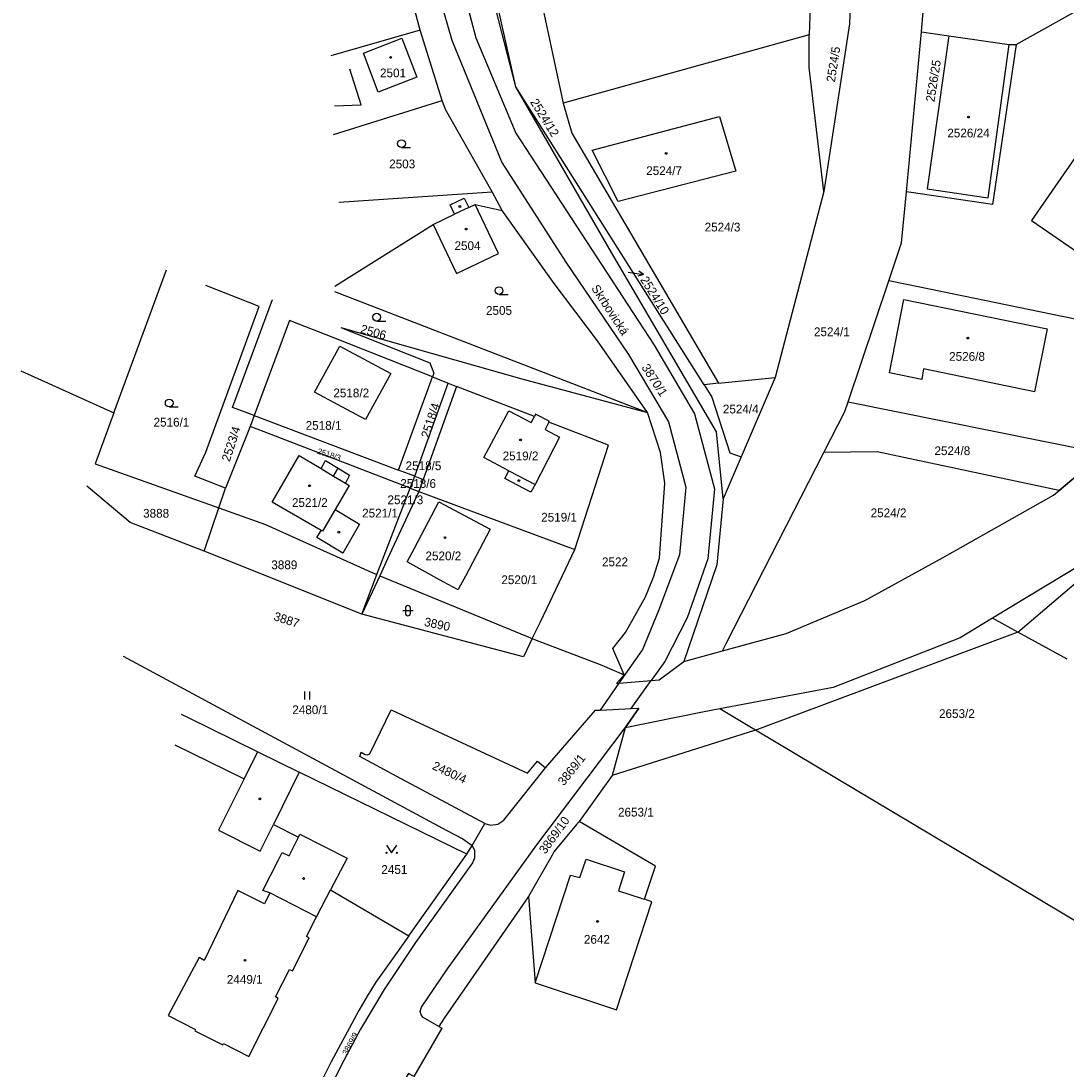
# Model space of a CAD drawing. Extents: x -527335 to -526256, y -1079142 to -1077809.
# Drawn here: x -527335.2 to -527132.2, y -1078645.5 to -1078442 of the extents above; entities that cross this region are included whole.
import ezdxf

# ---------------------------------------------------------------- set-up
doc = ezdxf.new("R2010")
doc.units = 0
for name, color, linetype in [('Vrstva 1', 7, 'Continuous'), ('Vrstva 2', 7, 'Continuous'), ('Vrstva 3', 7, 'Continuous'), ('Vrstva 4', 7, 'Continuous'), ('Vrstva 5', 7, 'Continuous'), ('Vrstva 54', 7, 'Continuous'), ('Vrstva 7', 7, 'Continuous')]:
    doc.layers.add(name, color=color, linetype=linetype)

msp = doc.modelspace()

# ---------------------------------------------------------------- linework, layer by layer
at = {"layer": 'Vrstva 1'}
for p, q in [((-527239.04, -1078454.82), (-527247.66, -1078421.31)), ((-527239.04, -1078454.82), (-527244.36, -1078431)), ((-527235.72, -1078430.51), (-527229.87, -1078457.96)), ((-527181.65, -1078433.18), (-527182.05, -1078444.72)), ((-527160.26, -1078444.15), (-527159.81, -1078439.41)), ((-527257.62, -1078443.82), (-527275, -1078448.78)), ((-527253.34, -1078457.46), (-527257.62, -1078443.82)), ((-527182.05, -1078444.72), (-527229.87, -1078457.96)), ((-527163.17, -1078475.2), (-527160.26, -1078444.15)), ((-527160.26, -1078444.15), (-527154.89, -1078444.92)), ((-527154.89, -1078444.92), (-527143.23, -1078446.59)), ((-527143.23, -1078446.59), (-527141.86, -1078446.59)), ((-527202.47, -1078512.66), (-527239.04, -1078454.82)), ((-527274.44, -1078464.05), (-527253.34, -1078457.46)), ((-527273.4, -1078477.22), (-527243.62, -1078475.21)), ((-527241.72, -1078478.83), (-527243.62, -1078475.21)), ((-527179.21, -1078475.16), (-527188.68, -1078511.23)), ((-527317.13, -1078518.14), (-527306.91, -1078490.33)), ((-527174.49, -1078515.96), (-527166.58, -1078492.47)), ((-527274.23, -1078494.55), (-527213.45, -1078518.05)), ((-527335.17, -1078509.94), (-527317.13, -1078518.14)), ((-527261.81, -1078529.25), (-527255.24, -1078511.13)), ((-527258.66, -1078530.43), (-527252.15, -1078512.35)), ((-527255.24, -1078511.13), (-527252.15, -1078512.35)), ((-527252.15, -1078512.35), (-527250.53, -1078512.99)), ((-527199.68, -1078512.37), (-527202.47, -1078512.66)), ((-527199.68, -1078512.37), (-527188.68, -1078511.23)), ((-527188.68, -1078511.23), (-527195.25, -1078526.63)), ((-527250.53, -1078512.99), (-527257.05, -1078531.04)), ((-527235.44, -1078518.84), (-527250.53, -1078512.99)), ((-527174.49, -1078515.96), (-527124.9, -1078525.93)), ((-527317.13, -1078518.14), (-527320.76, -1078528.03)), ((-527289.88, -1078518.66), (-527290.67, -1078520.76)), ((-527289.88, -1078518.66), (-527261.81, -1078529.25)), ((-527290.67, -1078520.76), (-527295.46, -1078532.72)), ((-527195.25, -1078526.63), (-527198.73, -1078534.79)), ((-527124.9, -1078525.93), (-527133.51, -1078533.2)), ((-527320.76, -1078528.03), (-527296.75, -1078536.57)), ((-527258.66, -1078530.43), (-527261.81, -1078529.25)), ((-527259.56, -1078532.72), (-527258.66, -1078530.43)), ((-527258.66, -1078530.43), (-527257.05, -1078531.04)), ((-527296.75, -1078536.57), (-527295.46, -1078532.72)), ((-527266.02, -1078549.53), (-527259.56, -1078532.72)), ((-527259.56, -1078532.72), (-527257.89, -1078533.36)), ((-527257.05, -1078531.04), (-527257.89, -1078533.36)), ((-527257.89, -1078533.36), (-527227.55, -1078544.64)), ((-527299.55, -1078544.94), (-527296.75, -1078536.57)), ((-527268.92, -1078557.21), (-527299.55, -1078544.94)), ((-527268.92, -1078557.21), (-527266.02, -1078549.53)), ((-527265.48, -1078549.77), (-527268.92, -1078557.21)), ((-527265.48, -1078549.77), (-527235.84, -1078561.93)), ((-527206.43, -1078566.42), (-527198.92, -1078564.35)), ((-527233.27, -1078587.02), (-527223.54, -1078575.86)), ((-527248.53, -1078603.79), (-527281.11, -1078587.88)), ((-527247.54, -1078602.12), (-527245.03, -1078597.85)), ((-527259.82, -1078619.66), (-527248.53, -1078603.79)), ((-527248.53, -1078603.79), (-527247.54, -1078602.12))]:
    msp.add_line(p, q, dxfattribs=at)
for points in [[(-527257.62, -1078443.82), (-527260.56, -1078432.84), (-527263.99, -1078416.01), (-527265.53, -1078409.01), (-527266.79, -1078407.04)], [(-527141.86, -1078446.59), (-527110.16, -1078428.84), (-527097.36, -1078410.28)], [(-527092.4, -1078413.63), (-527138.83, -1078480.75), (-527128.47, -1078487.92), (-527076.74, -1078413.16)], [(-527173.99, -1078435.36), (-527174.21, -1078442.61), (-527179.21, -1078475.16)], [(-527179.21, -1078475.16), (-527182.08, -1078451.08), (-527182.05, -1078444.72)], [(-527154.89, -1078444.92), (-527159.14, -1078474.62), (-527147.28, -1078476.36), (-527143.23, -1078446.59)], [(-527141.86, -1078446.59), (-527146.45, -1078477.67), (-527162.26, -1078475.33), (-527163.17, -1078475.2)], [(-527198.73, -1078534.79), (-527200.06, -1078521.8), (-527220.43, -1078486.97), (-527239.04, -1078454.82)], [(-527243.62, -1078475.21), (-527252.7, -1078459.24), (-527253.34, -1078457.46)], [(-527229.87, -1078457.96), (-527228.18, -1078463.81), (-527199.68, -1078512.37)], [(-527219.15, -1078477.07), (-527224.21, -1078467.12), (-527199.45, -1078460.61), (-527196.27, -1078471.22), (-527219.15, -1078477.07)], [(-527068.91, -1078470.58), (-527076.43, -1078483.63), (-527090.99, -1078506.94), (-527111.43, -1078532.12), (-527128.98, -1078547.4), (-527146.41, -1078557.97)], [(-527166.58, -1078492.47), (-527164.1, -1078485.12), (-527163.17, -1078475.2)], [(-527274.18, -1078493.5), (-527255.07, -1078481.53), (-527250.55, -1078491.03), (-527242.42, -1078487.16), (-527246.95, -1078477.65), (-527241.72, -1078478.83)], [(-527213.45, -1078518.05), (-527223.17, -1078504.16), (-527231.59, -1078492.99), (-527241.72, -1078478.83)], [(-527295.46, -1078532.72), (-527301.38, -1078530.43), (-527299.24, -1078525.73), (-527288.92, -1078497.44), (-527299.25, -1078493.36)], [(-527104.6, -1078505.26), (-527106.49, -1078504.87), (-527163.05, -1078493.2), (-527166.58, -1078492.47)], [(-527289.88, -1078518.66), (-527294.09, -1078517.07), (-527286.31, -1078496.08)], [(-527166.45, -1078510.36), (-527163.63, -1078496.12), (-527135.81, -1078501.81), (-527138.3, -1078514.05), (-527159.84, -1078509.57), (-527160.15, -1078511.61), (-527166.45, -1078510.36)], [(-527255.24, -1078511.13), (-527274.39, -1078503.57), (-527282.98, -1078500.18), (-527289.88, -1078518.66)], [(-527273.06, -1078501.52), (-527237.85, -1078511.53), (-527213.45, -1078518.05)], [(-527273.06, -1078501.52), (-527255.77, -1078508.43), (-527254.97, -1078510.38), (-527255.24, -1078511.13)], [(-527268.22, -1078519.41), (-527278.14, -1078514.11), (-527273.23, -1078505.19), (-527263.34, -1078510.46), (-527268.22, -1078519.41)], [(-527202.47, -1078512.66), (-527200.97, -1078515.04), (-527197.46, -1078525.86), (-527195.25, -1078526.63)], [(-527179.2, -1078525.81), (-527175.13, -1078517.85), (-527174.49, -1078515.96)], [(-527232.64, -1078519.92), (-527233.36, -1078521.36), (-527230.53, -1078522.83), (-527235.31, -1078532.02), (-527236.1, -1078533.53), (-527241.2, -1078530.87), (-527240.4, -1078529.35), (-527245.27, -1078526.81), (-527240.41, -1078517.7), (-527236.03, -1078519.97), (-527235.44, -1078518.84)], [(-527232.64, -1078519.92), (-527232.55, -1078519.75), (-527235.19, -1078518.36), (-527235.44, -1078518.84)], [(-527217.99, -1078568.99), (-527220.17, -1078563.88), (-527217.74, -1078560.78), (-527213.84, -1078553.85), (-527212.32, -1078550.03), (-527211.14, -1078546.31), (-527210.11, -1078531.79), (-527210.95, -1078525.81), (-527213.45, -1078518.05)], [(-527227.55, -1078544.64), (-527221.02, -1078524.42), (-527232.64, -1078519.92)], [(-527259.56, -1078532.72), (-527286.59, -1078522.33), (-527290.67, -1078520.76)], [(-527273.54, -1078528.84), (-527271.32, -1078530.24), (-527272.15, -1078531.75), (-527271.41, -1078532.19), (-527274.14, -1078536.87), (-527269.43, -1078539.75), (-527272.61, -1078545.33), (-527277.67, -1078542.33), (-527276.85, -1078540.95), (-527286.39, -1078535.46), (-527281.11, -1078526.41), (-527276.87, -1078528.94), (-527276.02, -1078527.39), (-527273.54, -1078528.84)], [(-527198.92, -1078564.35), (-527198.17, -1078562.88), (-527179.2, -1078525.81)], [(-527133.51, -1078533.2), (-527168.85, -1078525.7), (-527179.2, -1078525.81)], [(-527299.55, -1078544.94), (-527313.94, -1078539.4), (-527322.05, -1078532.59), (-527322.35, -1078532.34)], [(-527257.89, -1078533.36), (-527263.95, -1078546.46), (-527265.48, -1078549.77)], [(-527198.73, -1078534.79), (-527200, -1078547.64), (-527206.43, -1078566.42)], [(-527198.92, -1078564.35), (-527186.55, -1078560.94), (-527171.22, -1078554.58), (-527156.15, -1078546.29), (-527134.58, -1078534.1), (-527133.51, -1078533.2)], [(-527296.75, -1078536.57), (-527287.69, -1078539.8), (-527267.27, -1078548.97), (-527266.02, -1078549.53)], [(-527254, -1078535.37), (-527244.02, -1078540.72), (-527248.84, -1078549.81), (-527250.09, -1078552.15), (-527250.26, -1078552.48), (-527253.13, -1078550.9), (-527260.15, -1078547.05), (-527258.75, -1078544.4), (-527254, -1078535.37)], [(-527235.84, -1078561.93), (-527234.27, -1078558.66), (-527227.55, -1078544.64)], [(-527235.84, -1078561.93), (-527237.54, -1078565.48), (-527268.92, -1078557.21)], [(-527146.41, -1078557.97), (-527152.71, -1078561.79), (-527177.41, -1078571.47), (-527199.41, -1078575.6)], [(-527131.94, -1078565.93), (-527141.5, -1078560.67), (-527146.41, -1078557.97)], [(-527235.84, -1078561.93), (-527235.43, -1078562.1), (-527222.35, -1078567.12), (-527217.99, -1078568.99)], [(-527217.99, -1078568.99), (-527219.46, -1078570.65), (-527218.96, -1078570.61), (-527212.76, -1078570.1), (-527211.21, -1078569.97), (-527206.43, -1078566.42)], [(-527223.54, -1078575.86), (-527222.6, -1078575.81), (-527216.65, -1078575.51), (-527215.15, -1078575.44), (-527217.79, -1078579.29)], [(-527304.05, -1078576.62), (-527302.7, -1078577.25), (-527289.18, -1078583.91), (-527281.11, -1078587.88)], [(-527269.35, -1078584.85), (-527269.09, -1078584.02), (-527268.28, -1078584.48), (-527267.9, -1078584.54), (-527267.39, -1078584.35), (-527263.26, -1078575.8), (-527236.76, -1078588.08), (-527234.83, -1078585.74), (-527233.27, -1078587.02)], [(-527199.41, -1078575.6), (-527202.75, -1078576.23), (-527217.79, -1078579.29)], [(-527116.37, -1078625.34), (-527123.55, -1078620.8), (-527150.28, -1078604.87), (-527192.47, -1078579.74), (-527193.56, -1078579.08), (-527199.41, -1078575.6)], [(-527254.01, -1078637.26), (-527257.04, -1078635.52), (-527257.44, -1078634.99), (-527257.59, -1078634.32), (-527257.37, -1078633.52), (-527252.31, -1078626.07), (-527234.96, -1078601.97), (-527217.79, -1078579.29)], [(-527217.79, -1078579.29), (-527220.33, -1078588.55), (-527226.74, -1078597.44)], [(-527245.03, -1078597.85), (-527262.18, -1078588.7), (-527269.35, -1078584.85)], [(-527245.03, -1078597.85), (-527243.94, -1078598.18), (-527242.52, -1078597.99), (-527241.39, -1078597.17), (-527233.27, -1078587.02)], [(-527281.11, -1078587.88), (-527286.12, -1078598.02), (-527281.28, -1078600.51), (-527280.99, -1078599.93), (-527271.78, -1078604.56), (-527275.02, -1078610.72), (-527259.82, -1078619.66)], [(-527226.74, -1078597.44), (-527227.25, -1078598.03), (-527231.63, -1078603.34), (-527231.98, -1078604), (-527236.58, -1078612)], [(-527236.58, -1078612), (-527235.31, -1078628.81), (-527219.47, -1078634.01), (-527212.59, -1078613.04), (-527214.07, -1078612.55), (-527211.93, -1078606.15), (-527226.74, -1078597.44)], [(-527247.54, -1078602.12), (-527247.04, -1078603.09), (-527247.06, -1078604.56), (-527247.44, -1078605.48), (-527258.5, -1078620.92), (-527264.64, -1078630.06), (-527269.21, -1078637.79), (-527272.96, -1078644.85), (-527276.06, -1078651.14), (-527277.91, -1078656.32)], [(-527236.58, -1078612), (-527252.96, -1078635.63), (-527254.01, -1078637.26)], [(-527259.82, -1078619.66), (-527262.34, -1078623.21), (-527266.21, -1078628.65), (-527267.92, -1078631.37), (-527269.54, -1078634.12), (-527274.93, -1078644.11), (-527277.98, -1078650.21), (-527279.35, -1078653.36)], [(-527254.01, -1078637.26), (-527253.42, -1078637.6), (-527258.88, -1078646.96), (-527259.9, -1078646.35), (-527260.95, -1078647.97)]]:
    msp.add_lwpolyline(points, dxfattribs=at)
at = {"layer": 'Vrstva 3'}
for p, q in [((-527261.24, -1078466.6), (-527259.49, -1078466.6)), ((-527242.3, -1078495.13), (-527240.55, -1078495.13)), ((-527266.06, -1078500.29), (-527264.31, -1078500.29)), ((-527306.37, -1078516.95), (-527304.62, -1078516.95)), ((-527261, -1078556.52), (-527259, -1078556.52)), ((-527260.5, -1078556.02), (-527260.5, -1078557.02)), ((-527259.5, -1078557.02), (-527259.5, -1078556.02)), ((-527280.05, -1078573.74), (-527280.05, -1078572.24)), ((-527279.05, -1078573.74), (-527279.05, -1078572.24))]:
    msp.add_line(p, q, dxfattribs=at)
msp.add_lwpolyline([(-527264.17, -1078602.04), (-527263.17, -1078603.54), (-527262.17, -1078602.04)], dxfattribs=at)
for centre, radius in [((-527261.24, -1078465.85), 0.75), ((-527242.3, -1078494.38), 0.75), ((-527266.06, -1078499.54), 0.75), ((-527306.37, -1078516.2), 0.75), ((-527264.17, -1078603.54), 0.1), ((-527262.17, -1078603.54), 0.1)]:
    msp.add_circle(centre, radius, dxfattribs=at)
for centre, start, end in [((-527260, -1078556.02), 0, 180), ((-527260, -1078557.02), 180, 359.9879)]:
    msp.add_arc(centre, 0.5, start, end, dxfattribs=at)
at = {"layer": 'Vrstva 4'}
for p, q in [((-527257.19, -1078425.85), (-527251.49, -1078445.79)), ((-527252.03, -1078425.08), (-527246.83, -1078445.33)), ((-527268.65, -1078448.3), (-527261.15, -1078445.39)), ((-527261.15, -1078445.39), (-527258.29, -1078452.93)), ((-527251.49, -1078445.79), (-527241.75, -1078469.5)), ((-527246.83, -1078445.33), (-527239.01, -1078463.8)), ((-527265.8, -1078455.86), (-527268.65, -1078448.3)), ((-527269.08, -1078458.33), (-527271.25, -1078451.41)), ((-527258.29, -1078452.93), (-527265.8, -1078455.86)), ((-527274.24, -1078458.53), (-527269.08, -1078458.33)), ((-527239.01, -1078463.8), (-527224.34, -1078486.36)), ((-527241.75, -1078469.5), (-527229.3, -1078488.84)), ((-527251.82, -1078477.73), (-527249.06, -1078476.42)), ((-527250.95, -1078479.56), (-527251.82, -1078477.73)), ((-527249.06, -1078476.42), (-527248.19, -1078478.25)), ((-527248.19, -1078478.25), (-527246.95, -1078477.65)), ((-527255.07, -1078481.53), (-527250.95, -1078479.56)), ((-527248.19, -1078478.25), (-527250.95, -1078479.56)), ((-527224.34, -1078486.36), (-527212.18, -1078504.95)), ((-527229.3, -1078488.84), (-527217.18, -1078506.82)), ((-527212.18, -1078504.95), (-527204.34, -1078518.29)), ((-527217.18, -1078506.82), (-527209.4, -1078519.86)), ((-527204.34, -1078518.29), (-527200.47, -1078532.85)), ((-527209.4, -1078519.86), (-527206.04, -1078532.55)), ((-527276.87, -1078528.94), (-527274.45, -1078530.38)), ((-527274.45, -1078530.38), (-527273.54, -1078528.84)), ((-527274.45, -1078530.38), (-527272.15, -1078531.75)), ((-527240.4, -1078529.35), (-527235.31, -1078532.02)), ((-527206.04, -1078532.55), (-527207.21, -1078545.66)), ((-527200.47, -1078532.85), (-527201.76, -1078546.48)), ((-527141.5, -1078560.67), (-527109.01, -1078533.01)), ((-527274.14, -1078536.87), (-527276.6, -1078541.09)), ((-527276.6, -1078541.09), (-527276.85, -1078540.95)), ((-527207.21, -1078545.66), (-527211.24, -1078556.37)), ((-527201.76, -1078546.48), (-527205.76, -1078557.93)), ((-527211.24, -1078556.37), (-527214.52, -1078564.26)), ((-527205.76, -1078557.93), (-527210.09, -1078566.38)), ((-527141.5, -1078560.67), (-527192.07, -1078579.61)), ((-527315.29, -1078565.33), (-527252.47, -1078599.22)), ((-527218.96, -1078570.61), (-527214.52, -1078564.26)), ((-527210.09, -1078566.38), (-527212.76, -1078570.1)), ((-527222.6, -1078575.81), (-527218.96, -1078570.61)), ((-527216.65, -1078575.51), (-527212.76, -1078570.1)), ((-527192.47, -1078579.74), (-527220.33, -1078588.55)), ((-527192.07, -1078579.61), (-527192.47, -1078579.74)), ((-527305.27, -1078582.54), (-527291.79, -1078589.15)), ((-527291.79, -1078589.15), (-527289.18, -1078583.91)), ((-527291.79, -1078589.15), (-527296.8, -1078599.13)), ((-527296.8, -1078599.13), (-527288.7, -1078603.23)), ((-527288.7, -1078603.23), (-527286.12, -1078598.02)), ((-527252.47, -1078599.22), (-527249.31, -1078600.83)), ((-527249.31, -1078600.83), (-527247.54, -1078602.12)), ((-527226.61, -1078608.33), (-527225.35, -1078604.75)), ((-527225.35, -1078604.75), (-527217.95, -1078607.21)), ((-527235.31, -1078628.81), (-527228.42, -1078607.88)), ((-527228.42, -1078607.88), (-527226.61, -1078608.33)), ((-527217.95, -1078607.21), (-527219.07, -1078610.9)), ((-527293.03, -1078610.82), (-527299.57, -1078624.44)), ((-527287.83, -1078613.47), (-527293.03, -1078610.82)), ((-527286.82, -1078611.29), (-527287.83, -1078613.47)), ((-527277.77, -1078615.94), (-527286.82, -1078611.29)), ((-527277.77, -1078615.94), (-527275.02, -1078610.72)), ((-527219.07, -1078610.9), (-527214.52, -1078612.4)), ((-527214.52, -1078612.4), (-527214.07, -1078612.55)), ((-527279.72, -1078619.78), (-527277.77, -1078615.94)), ((-527282.45, -1078626.45), (-527279.19, -1078620.05)), ((-527279.19, -1078620.05), (-527279.72, -1078619.78)), ((-527300.52, -1078623.89), (-527306.58, -1078635.1)), ((-527299.57, -1078624.44), (-527300.52, -1078623.89)), ((-527285.72, -1078631.52), (-527282.99, -1078626.17)), ((-527282.99, -1078626.17), (-527282.45, -1078626.45)), ((-527290.93, -1078643.06), (-527285.18, -1078631.79)), ((-527285.18, -1078631.79), (-527285.72, -1078631.52)), ((-527306.58, -1078635.1), (-527301.23, -1078637.82)), ((-527301.23, -1078637.82), (-527301.36, -1078638.08)), ((-527301.36, -1078638.08), (-527295.95, -1078640.84)), ((-527295.95, -1078640.84), (-527295.82, -1078640.57)), ((-527295.82, -1078640.57), (-527290.93, -1078643.06))]:
    msp.add_line(p, q, dxfattribs=at)
for points in [[(-527285.18, -1078605.01), (-527284.4, -1078603.5), (-527283.09, -1078604.13), (-527281.28, -1078600.51)], [(-527286.82, -1078611.29), (-527288.18, -1078610.84), (-527285.18, -1078605.01)]]:
    msp.add_lwpolyline(points, dxfattribs=at)
at = {"layer": 'Vrstva 5'}
for centre in [(-527263.35, -1078449.1), (-527151.12, -1078460.69), (-527209.83, -1078467.74), (-527249.92, -1078478.05), (-527248.67, -1078482.43), (-527151.22, -1078503.6), (-527238.13, -1078523.37), (-527279.1, -1078532.27), (-527238.44, -1078531.27), (-527273.44, -1078541.28), (-527252.8, -1078542.34), (-527288.74, -1078593.05), (-527280.25, -1078608.51), (-527223.15, -1078616.85), (-527291.65, -1078624.4)]:
    msp.add_circle(centre, 0.175, dxfattribs=at)
at = {"layer": 'Vrstva 54'}
for points in [[(-527211.21, -1078569.97), (-527206.43, -1078566.42), (-527198.92, -1078564.35), (-527186.55, -1078560.94), (-527171.22, -1078554.58), (-527156.15, -1078546.29), (-527134.58, -1078534.1), (-527133.51, -1078533.2), (-527124.9, -1078525.93), (-527119.69, -1078521.54), (-527104.6, -1078505.26), (-527102.68, -1078503.19), (-527093.38, -1078489.99), (-527078.2, -1078464.76), (-527073.97, -1078460.17), (-527053.17, -1078420.48)], [(-527044.07, -1078424.46), (-527066.65, -1078463.1), (-527068.91, -1078470.58), (-527090.99, -1078506.94), (-527111.43, -1078532.12), (-527128.98, -1078547.4), (-527146.41, -1078557.97), (-527152.71, -1078561.79), (-527177.41, -1078571.47), (-527199.41, -1078575.6), (-527202.75, -1078576.23), (-527217.79, -1078579.29), (-527215.15, -1078575.44)]]:
    msp.add_lwpolyline(points, dxfattribs=at)
at = {"layer": 'Vrstva 7'}
for p, q in [((-527217.22, -1078490.78), (-527214.26, -1078491.25)), ((-527214.26, -1078491.25), (-527215.32, -1078491.59)), ((-527214.26, -1078491.25), (-527215.17, -1078490.6))]:
    msp.add_line(p, q, dxfattribs=at)

# ---------------------------------------------------------------- texts
at = {"layer": 'Vrstva 2'}
for s, height, rotation, p in [('2524/5', 1.7, 81, (-527177.06, -1078454.01)), ('2526/25', 1.7, 81, (-527157.73, -1078457.85)), ('2524/12', 1.7, 302, (-527236.32, -1078457.78)), ('2524/10', 1.7, 302, (-527214.93, -1078492.27)), ('2506', 1.7, 344, (-527269.36, -1078502.54)), ('3870/1', 1.7, 303, (-527214.69, -1078509.31)), ('2518/4', 1.7, 72, (-527255.89, -1078523.16)), ('2523/4', 1.7, 72, (-527294.62, -1078527.71)), ('2518/3', 1.139, 342, (-527277.7, -1078526.03)), ('3887', 1.7, 342, (-527286.22, -1078558.32)), ('3890', 1.7, 348, (-527256.95, -1078559.46)), ('3869/1', 1.7, 51.4372, (-527229.71, -1078590.63)), ('2480/4', 1.7, 335, (-527255.42, -1078587.23)), ('3869/10', 1.7, 54, (-527233.31, -1078603.91)), ('3869/9', 1.139, 62, (-527271.81, -1078642.9))]:
    msp.add_text(s, height=height, rotation=rotation, dxfattribs=at).set_placement(p)
for s, p in [('2501', (-527265.42, -1078452.97)), ('2526/24', (-527155.21, -1078464.64)), ('2503', (-527263.64, -1078470.64)), ('2524/7', (-527213.71, -1078471.95)), ('2524/3', (-527202.36, -1078482.9)), ('2504', (-527250.95, -1078486.51)), ('2505', (-527244.83, -1078499.09)), ('2524/1', (-527181.12, -1078503.23)), ('2526/8', (-527154.86, -1078508.01)), ('2518/2', (-527274.49, -1078515.1)), ('2524/4', (-527198.82, -1078518.23)), ('2516/1', (-527309.41, -1078520.78)), ('2518/1', (-527279.86, -1078521.41)), ('2524/8', (-527157.71, -1078526.32)), ('2519/2', (-527241.6, -1078527.33)), ('2518/5', (-527260.45, -1078529.24)), ('2518/6', (-527261.49, -1078532.68)), ('2521/2', (-527282.53, -1078536.38)), ('2521/3', (-527263.97, -1078535.85)), ('3888', (-527311.44, -1078538.47)), ('2521/1', (-527268.89, -1078538.43)), ('2524/2', (-527170.11, -1078538.38)), ('2519/1', (-527234.11, -1078539.23)), ('2520/2', (-527256.59, -1078546.74)), ('3889', (-527286.54, -1078548.47)), ('2522', (-527222.3, -1078547.9)), ('2520/1', (-527241.84, -1078551.37)), ('2480/1', (-527282.46, -1078576.61)), ('2653/2', (-527156.83, -1078577.36)), ('2653/1', (-527219.19, -1078596.49)), ('2451', (-527265.16, -1078607.63)), ('2642', (-527225.81, -1078621.19)), ('2449/1', (-527295.17, -1078628.96))]:
    msp.add_text(s, height=1.7, dxfattribs=at).set_placement(p)
at = {"layer": 'Vrstva 7'}
msp.add_text('Skrbovická', height=1.7, rotation=303, dxfattribs=at).set_placement((-527224.45, -1078493.92))

doc.saveas('drawing.dxf')
